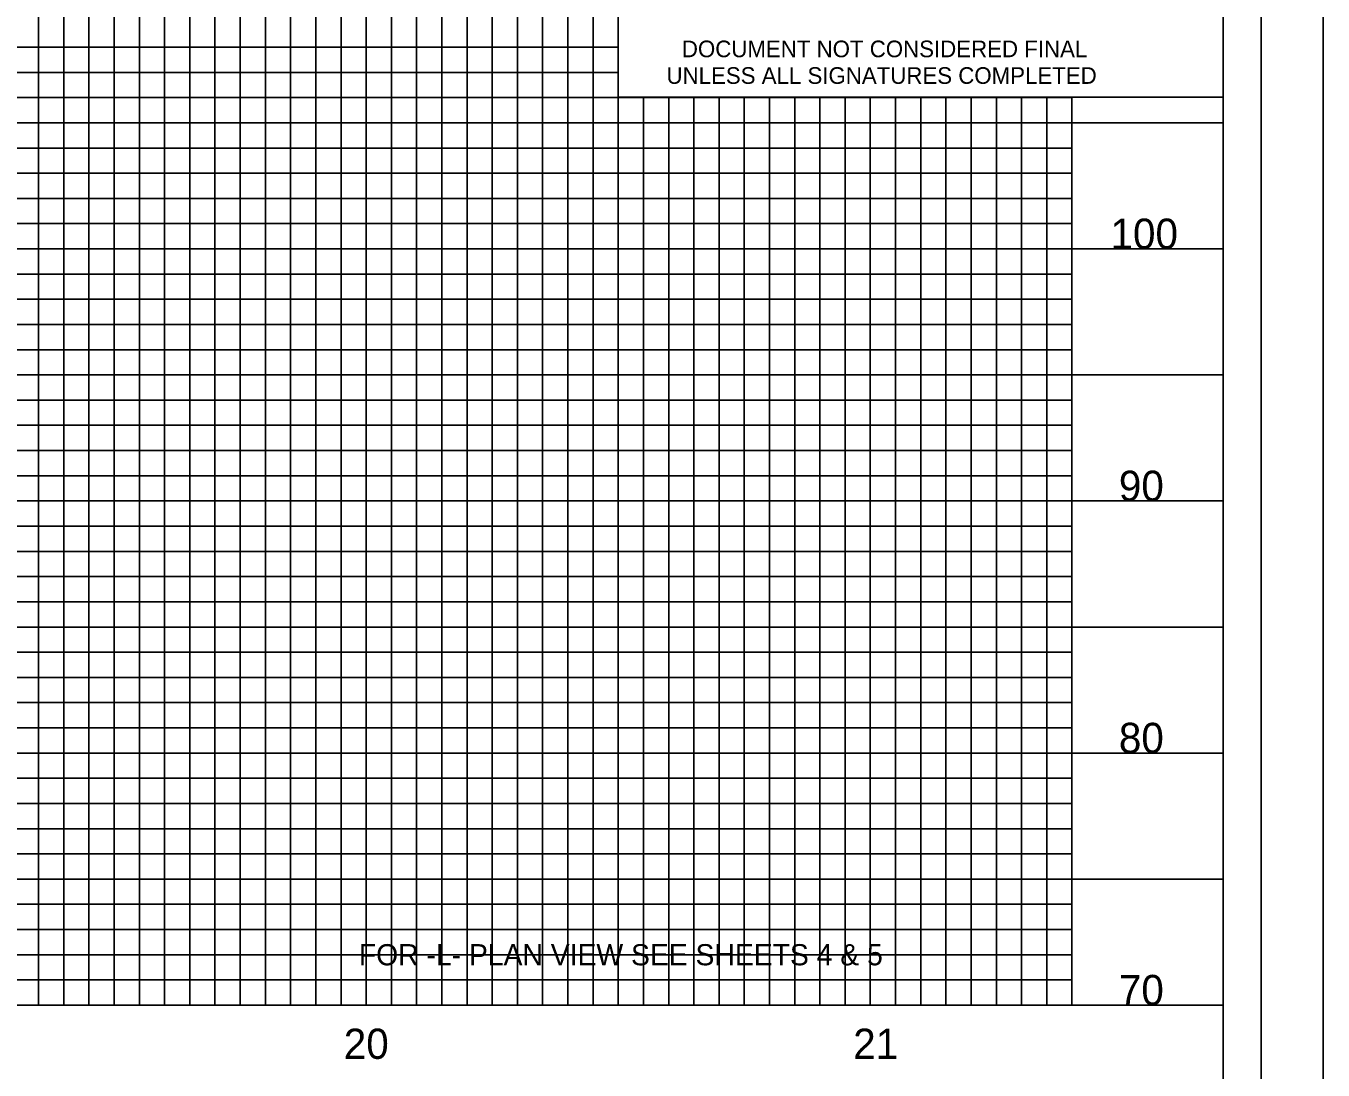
# Model space of a CAD drawing. Extents: x 2113883 to 2114903, y 714180 to 714840.
# Drawn here: x 2114645.3 to 2114902.6, y 714512.4 to 714719.5 of the extents above; entities that cross this region are included whole.
import ezdxf

# ---------------------------------------------------------------- set-up
doc = ezdxf.new("R2010")
doc.units = 0
for name, color, linetype in [('Exist Vertical Profile Horizontal Axis Label Major', 7, 'Continuous'), ('Exist Vertical Profile Vertical Axis Label', 7, 'Continuous'), ('Prop Grid Mask', 7, 'Continuous'), ('Prop PFL Text', 7, 'Continuous'), ('Sheet Cutting Line CELL', 7, 'Continuous'), ('Sheet Layout Profile Border Port 1', 7, 'Continuous'), ('Sheet Plot Border Inside CELL', 7, 'Continuous'), ('Sheet Plot Border Outside CELL', 7, 'Continuous'), ('Sheet Profile CELL', 7, 'Continuous'), ('Sheet Profile Grid Major CELL', 7, 'Continuous'), ('Sheet Profile Grid Middle CELL', 7, 'Continuous'), ('Sheet Profile Grid Minor CELL', 7, 'Continuous'), ('Sheet Sticker Exception Certification CELL', 7, 'Continuous')]:
    doc.layers.add(name, color=color, linetype=linetype)

msp = doc.modelspace()

# ---------------------------------------------------------------- linework, layer by layer
at = {"layer": 'Prop Grid Mask'}
msp.add_lwpolyline([(2114702.76, 714540.29), (2114847.76, 714540.29), (2114847.76, 714530.29), (2114702.76, 714530.29)], close=True, dxfattribs=at)
at = {"layer": 'Prop PFL Text'}
msp.add_lwpolyline([(2114702.76, 714540.29), (2114847.76, 714540.29), (2114847.76, 714530.29), (2114702.76, 714530.29)], close=True, dxfattribs=at)
at = {"layer": 'Sheet Cutting Line CELL'}
msp.add_line((2114902.56, 714180.29), (2114902.56, 714840.29), dxfattribs=at)
at = {"layer": 'Sheet Layout Profile Border Port 1'}
msp.add_lwpolyline([(2114012.76, 714825.29), (2114762.73, 714825.29), (2114762.73, 714705.41), (2114852.76, 714705.29), (2114852.76, 714525.29), (2114012.76, 714525.29)], close=True, dxfattribs=at)
at = {"layer": 'Sheet Plot Border Inside CELL'}
msp.add_lwpolyline([(2113890.36, 714193.76), (2114890.26, 714193.76), (2114890.26, 714826.82), (2113890.36, 714826.82)], close=True, dxfattribs=at)
at = {"layer": 'Sheet Plot Border Outside CELL'}
msp.add_lwpolyline([(2113882.56, 714180.29), (2114902.56, 714180.29), (2114902.56, 714840.29), (2113882.56, 714840.29)], close=True, dxfattribs=at)
at = {"layer": 'Sheet Profile CELL'}
msp.add_line((2113982.76, 714525.29), (2114882.76, 714525.29), dxfattribs=at)
msp.add_lwpolyline([(2114882.76, 714825.29), (2113982.76, 714825.29), (2113982.76, 714195.29), (2114882.76, 714195.29)], close=True, dxfattribs=at)
at = {"layer": 'Sheet Profile Grid Major CELL'}
for p, q in [((2114662.76, 714825.29), (2114662.76, 714525.29)), ((2114687.76, 714825.29), (2114687.76, 714525.29)), ((2114712.76, 714825.29), (2114712.76, 714525.29)), ((2114737.76, 714825.29), (2114737.76, 714525.29)), ((2114762.76, 714825.29), (2114762.76, 714525.29)), ((2114787.76, 714705.41), (2114787.76, 714525.29)), ((2114812.76, 714705.41), (2114812.76, 714525.29)), ((2114837.76, 714705.41), (2114837.76, 714525.29)), ((2114852.76, 714705.41), (2114852.76, 714525.29)), ((2113982.76, 714700.29), (2114882.76, 714700.29)), ((2114882.76, 714675.29), (2113982.76, 714675.29)), ((2113982.76, 714650.29), (2114882.76, 714650.29)), ((2114882.76, 714625.29), (2113982.76, 714625.29)), ((2113982.76, 714600.29), (2114882.76, 714600.29)), ((2114882.76, 714575.29), (2113982.76, 714575.29)), ((2113982.76, 714550.29), (2114882.76, 714550.29))]:
    msp.add_line(p, q, dxfattribs=at)
at = {"layer": 'Sheet Profile Grid Middle CELL'}
for p, q in [((2114012.76, 714715.29), (2114762.76, 714715.29)), ((2114012.76, 714710.29), (2114762.76, 714710.29)), ((2114012.76, 714705.29), (2114852.76, 714705.29)), ((2114012.76, 714695.29), (2114852.76, 714695.29)), ((2114012.76, 714690.29), (2114852.76, 714690.29)), ((2114012.76, 714685.29), (2114852.76, 714685.29)), ((2114012.76, 714680.29), (2114852.76, 714680.29)), ((2114012.76, 714670.29), (2114852.76, 714670.29)), ((2114012.76, 714665.29), (2114852.76, 714665.29)), ((2114012.76, 714660.29), (2114852.76, 714660.29)), ((2114012.76, 714655.29), (2114852.76, 714655.29)), ((2114012.76, 714645.29), (2114852.76, 714645.29)), ((2114012.76, 714640.29), (2114852.76, 714640.29)), ((2114012.76, 714635.29), (2114852.76, 714635.29)), ((2114012.76, 714630.29), (2114852.76, 714630.29)), ((2114012.76, 714620.29), (2114852.76, 714620.29)), ((2114012.76, 714615.29), (2114852.76, 714615.29)), ((2114012.76, 714610.29), (2114852.76, 714610.29)), ((2114012.76, 714605.29), (2114852.76, 714605.29)), ((2114012.76, 714595.29), (2114852.76, 714595.29)), ((2114012.76, 714590.29), (2114852.76, 714590.29)), ((2114012.76, 714585.29), (2114852.76, 714585.29)), ((2114012.76, 714580.29), (2114852.76, 714580.29)), ((2114012.76, 714570.29), (2114852.76, 714570.29)), ((2114012.76, 714565.29), (2114852.76, 714565.29)), ((2114012.76, 714560.29), (2114852.76, 714560.29)), ((2114012.76, 714555.29), (2114852.76, 714555.29)), ((2114012.76, 714545.29), (2114852.76, 714545.29)), ((2114012.76, 714540.29), (2114852.76, 714540.29)), ((2114012.76, 714535.29), (2114852.76, 714535.29)), ((2114012.76, 714530.29), (2114852.76, 714530.29))]:
    msp.add_line(p, q, dxfattribs=at)
msp.add_lwpolyline([(2114777.76, 714690.29), (2114852.76, 714690.29)], dxfattribs=at)
at = {"layer": 'Sheet Profile Grid Minor CELL'}
for p, q in [((2114647.76, 714825.29), (2114647.76, 714525.29)), ((2114652.76, 714825.29), (2114652.76, 714525.29)), ((2114657.76, 714825.29), (2114657.76, 714525.29)), ((2114667.76, 714825.29), (2114667.76, 714525.29)), ((2114672.76, 714825.29), (2114672.76, 714525.29)), ((2114677.76, 714825.29), (2114677.76, 714525.29)), ((2114682.76, 714825.29), (2114682.76, 714525.29)), ((2114692.76, 714825.29), (2114692.76, 714525.29)), ((2114697.76, 714825.29), (2114697.76, 714525.29)), ((2114702.76, 714825.29), (2114702.76, 714525.29)), ((2114707.76, 714825.29), (2114707.76, 714525.29)), ((2114717.76, 714825.29), (2114717.76, 714525.29)), ((2114722.76, 714825.29), (2114722.76, 714525.29)), ((2114727.76, 714825.29), (2114727.76, 714525.29)), ((2114732.76, 714825.29), (2114732.76, 714525.29)), ((2114742.76, 714825.29), (2114742.76, 714525.29)), ((2114747.76, 714825.29), (2114747.76, 714525.29)), ((2114752.76, 714825.29), (2114752.76, 714525.29)), ((2114757.76, 714825.29), (2114757.76, 714525.29)), ((2114767.76, 714705.41), (2114767.76, 714525.29)), ((2114772.76, 714705.41), (2114772.76, 714525.29)), ((2114777.76, 714705.41), (2114777.76, 714525.29)), ((2114782.76, 714705.41), (2114782.76, 714525.29)), ((2114792.76, 714705.41), (2114792.76, 714525.29)), ((2114797.76, 714705.41), (2114797.76, 714525.29)), ((2114802.76, 714705.41), (2114802.76, 714525.29)), ((2114807.76, 714705.41), (2114807.76, 714525.29)), ((2114817.76, 714705.41), (2114817.76, 714525.29)), ((2114822.76, 714705.41), (2114822.76, 714525.29)), ((2114827.76, 714705.41), (2114827.76, 714525.29)), ((2114832.76, 714705.41), (2114832.76, 714525.29)), ((2114842.76, 714705.41), (2114842.76, 714525.29)), ((2114847.76, 714705.41), (2114847.76, 714525.29))]:
    msp.add_line(p, q, dxfattribs=at)
at = {"layer": 'Sheet Sticker Exception Certification CELL'}
for p, q in [((2114762.73, 714705.41), (2114762.73, 714719.51)), ((2114882.76, 714719.5), (2114882.76, 714705.4)), ((2114882.76, 714705.41), (2114762.73, 714705.41))]:
    msp.add_line(p, q, dxfattribs=at)

# ---------------------------------------------------------------- texts
at = {"layer": 'Exist Vertical Profile Horizontal Axis Label Major'}
for s, p in [('20', (2114708.31, 714514.63)), ('20', (2114708.31, 714514.63)), ('20', (2114708.31, 714514.63)), ('20', (2114708.31, 714514.63)), ('21', (2114809.36, 714514.63)), ('21', (2114809.36, 714514.63)), ('21', (2114809.36, 714514.63)), ('21', (2114809.36, 714514.63))]:
    msp.add_text(s, height=6, dxfattribs=at).set_placement(p)
at = {"layer": 'Exist Vertical Profile Vertical Axis Label'}
for s, p in [('100', (2114860.4, 714675.29)), ('90', (2114862.06, 714625.29)), ('80', (2114862.06, 714575.29)), ('70', (2114862.06, 714525.29))]:
    msp.add_text(s, height=6, dxfattribs=at).set_placement(p)
at = {"layer": 'Prop PFL Text'}
msp.add_text('FOR -L- PLAN VIEW SEE SHEETS 4 & 5', height=4.2, dxfattribs=at).set_placement((2114711.3, 714533.19))
at = {"layer": 'Sheet Sticker Exception Certification CELL'}
for s, p in [('DOCUMENT NOT CONSIDERED FINAL', (2114775.38, 714713.3)), ('UNLESS ALL SIGNATURES COMPLETED', (2114772.33, 714708.02))]:
    msp.add_text(s, height=3.3, rotation=0, dxfattribs=at).set_placement(p)

doc.saveas('drawing.dxf')
